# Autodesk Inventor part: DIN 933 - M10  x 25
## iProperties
Created: 2006-02
Part Number: DIN 933 - M10  x 25
Material: Steel, Mild
Description: Hex-Head Bolt
Document SubType Name: Modeling
Standard: DIN 933
Designer: Phil Trethewie
Standards Organization: DIN
Language: en-US
Size Designation: M10  x 25
Categories: <MemberInstance><Categories><Category DisplayName="Fasteners" InternalName="e4da775c-781d-43d5-af7c-5136215cf5a6" Mnemonic="FSTN"><Category DisplayName="Bolts"
IsCustomPart: 1
Author: Phil Trethewie
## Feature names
1. Body [Revolution]
2. Head [Extrusion]
3. Chamfer1 [Revolution]
4. Chamfer2
